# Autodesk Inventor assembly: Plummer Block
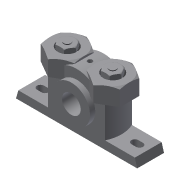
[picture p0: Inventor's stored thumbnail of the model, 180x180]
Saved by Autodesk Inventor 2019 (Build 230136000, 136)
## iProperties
Created: 2011-07
Part Number: Plummer Block
Document SubType Name: Assembly
Designer: CadCim
Author: CadCim
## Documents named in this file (7)
- E:\_Deepak\Inventor\Projects\Autodesk Inventor_2019_Project\Resources\Inventor_2018_tut\c09_Inv_2019_tut\c09_Inv_tut_2019\c09_tut02_inv\Plummer Block\Plummer Block.iam
- E:\_Deepak\Inventor\Projects\Autodesk Inventor_2019_Project\Resources\Inventor_2018_tut\c09_Inv_2019_tut\c09_Inv_tut_2019\c09_tut02_inv\Plummer Block\Casting.ipt
- E:\_Deepak\Inventor\Projects\Autodesk Inventor_2019_Project\Resources\Inventor_2018_tut\c09_Inv_2019_tut\c09_Inv_tut_2019\c09_tut02_inv\Plummer Block\Brasses.ipt
- E:\_Deepak\Inventor\Projects\Autodesk Inventor_2019_Project\Resources\Inventor_2018_tut\c09_Inv_2019_tut\c09_Inv_tut_2019\c09_tut02_inv\Plummer Block\Cap.ipt
- E:\_Deepak\Inventor\Projects\Autodesk Inventor_2019_Project\Resources\Inventor_2018_tut\c09_Inv_2019_tut\c09_Inv_tut_2019\c09_tut02_inv\Plummer Block\Bolt.ipt
- C:\inventor\c09\Butterfly Valve\Nut.ipt
- E:\_Deepak\Inventor\Projects\Autodesk Inventor_2019_Project\Resources\Inventor_2018_tut\c09_Inv_2019_tut\c09_Inv_tut_2019\c09_tut02_inv\Plummer Block\Lock Nut.ipt
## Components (9 placed, 6 different names)
1. Casting:1 — Mate:1, Mate:2, Insert:1, Angle:1, Insert:2, Angle:2
2. Brasses:1 — Mate:1, Mate:2, Mate:3, Mate:4
3. Cap:1 — Mate:3, Mate:4, Insert:4, Insert:5
4. Bolt:1 — Insert:1, Angle:1
5. Bolt:2 — Insert:2, Angle:2
6. Nut:2 — Insert:4, Insert:7
7. Nut:3 — Insert:5, Insert:6
8. Lock Nut:3 — Insert:6
9. Lock Nut:4 — Insert:7
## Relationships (12: Insert 6, Mate 4, Angle 2)
- Mate:1: Casting:1 ↔ Brasses:1
- Mate:2: Casting:1 ↔ Brasses:1
- Mate:3: Brasses:1 ↔ Cap:1
- Mate:4: Brasses:1 ↔ Cap:1
- Insert:1: Casting:1 ↔ Bolt:1
- Angle:1: Casting:1 ↔ Bolt:1
- Insert:2: Casting:1 ↔ Bolt:2
- Angle:2: Casting:1 ↔ Bolt:2
- Insert:4: Cap:1 ↔ Nut:2
- Insert:5: Cap:1 ↔ Nut:3
- Insert:6: Nut:3 ↔ Lock Nut:3
- Insert:7: Nut:2 ↔ Lock Nut:4
